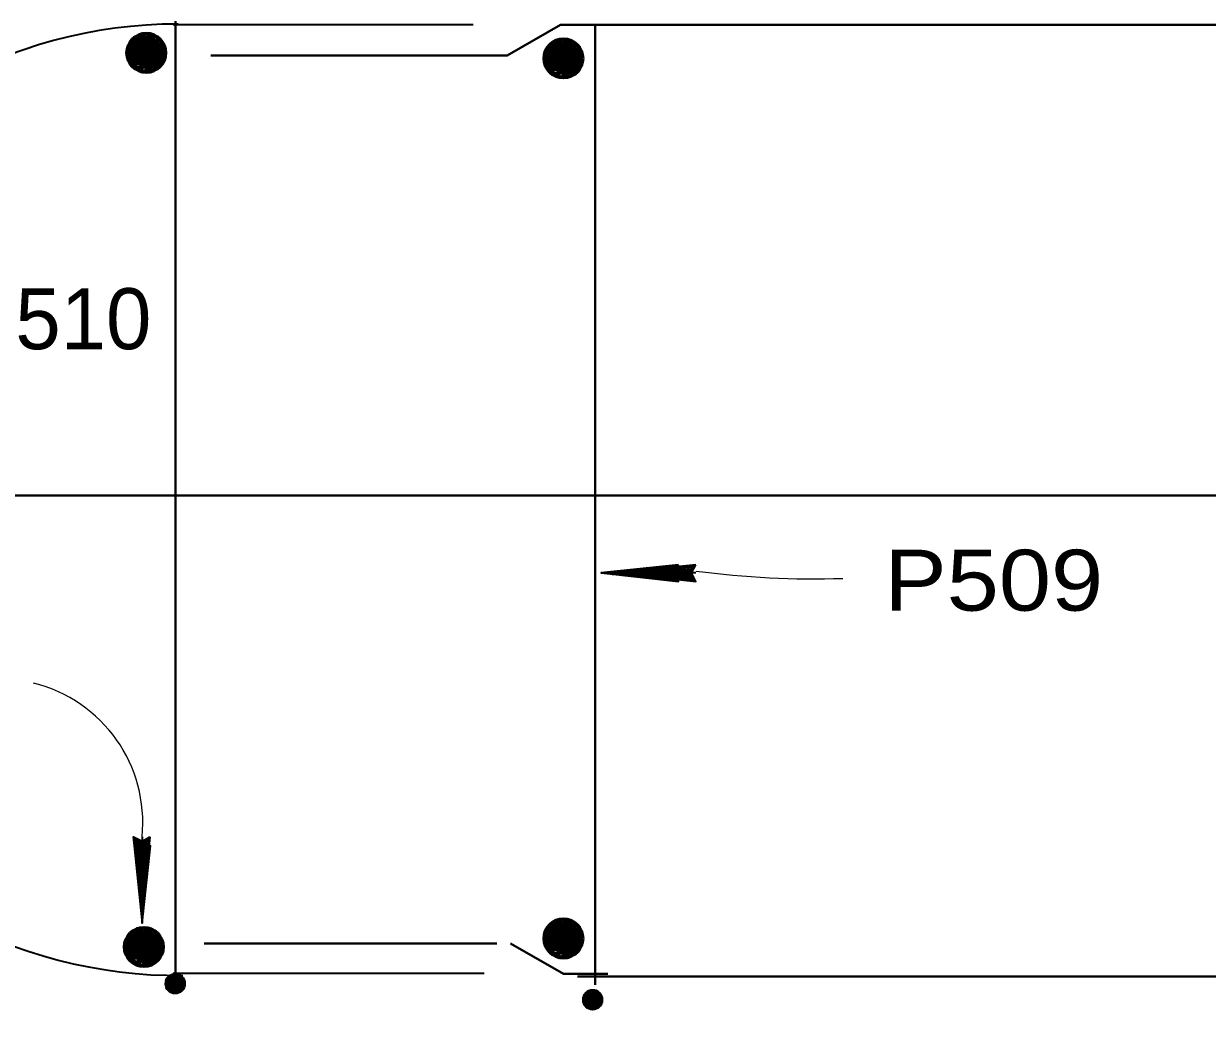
# Model space of a CAD drawing. Extents: x 3.64 to 6.84, y -0.8 to 1.19.
# Drawn here: x 4.0955 to 4.2572, y 0.714 to 0.852 of the extents above; entities that cross this region are included whole.
import ezdxf

# ---------------------------------------------------------------- set-up
doc = ezdxf.new("R2010")
doc.units = 0
doc.header["$LTSCALE"] = 0.0033
doc.layers.add('1', color=7, linetype='Continuous', lineweight=40)

msp = doc.modelspace()

# ---------------------------------------------------------------- linework, layer by layer
at = {"layer": '1', "lineweight": 35}
for p, q in [((4.115917, 0.851917), (4.156917, 0.851917)), ((4.185, 0.776917), (4.174417, 0.776917)), ((4.187333, 0.776917), (4.17675, 0.776917)), ((4.18475, 0.777917), (4.176917, 0.777)), ((4.18475, 0.777917), (4.176917, 0.777)), ((4.18475, 0.777833), (4.176917, 0.777)), ((4.18475, 0.77775), (4.176917, 0.776917)), ((4.18475, 0.77775), (4.176917, 0.77675)), ((4.18475, 0.776083), (4.177417, 0.776917)), ((4.18475, 0.776), (4.177417, 0.77675)), ((4.18475, 0.775833), (4.177417, 0.776667)), ((4.184833, 0.77625), (4.1775, 0.777)), ((4.187083, 0.777917), (4.17925, 0.777)), ((4.187083, 0.777917), (4.17925, 0.777)), ((4.187083, 0.777833), (4.17925, 0.777)), ((4.187083, 0.77775), (4.17925, 0.776917)), ((4.187083, 0.77775), (4.17925, 0.77675)), ((4.187083, 0.776083), (4.17975, 0.776917)), ((4.187083, 0.776), (4.17975, 0.77675)), ((4.187083, 0.775833), (4.17975, 0.776667)), ((4.187167, 0.77625), (4.179833, 0.777)), ((4.110583, 0.740583), (4.111417, 0.73325)), ((4.110667, 0.739333), (4.111583, 0.7315)), ((4.110667, 0.739333), (4.111583, 0.7315)), ((4.11075, 0.740583), (4.1115, 0.73325)), ((4.11075, 0.739333), (4.111583, 0.7315)), ((4.110833, 0.740583), (4.111667, 0.73325)), ((4.110833, 0.739333), (4.111667, 0.7315)), ((4.110833, 0.739333), (4.111833, 0.7315)), ((4.111, 0.740667), (4.11175, 0.733333)), ((4.1125, 0.740583), (4.1115, 0.73275)), ((4.112333, 0.739417), (4.111583, 0.732083)), ((4.111667, 0.740833), (4.111667, 0.73025)), ((4.1125, 0.740583), (4.111667, 0.73275)), ((4.111667, 0.739583), (4.111667, 0.729)), ((4.1125, 0.739333), (4.111667, 0.732)), ((4.112667, 0.740583), (4.11175, 0.73275)), ((4.112667, 0.740583), (4.11175, 0.73275)), ((4.112583, 0.740583), (4.11175, 0.73275)), ((4.112583, 0.739333), (4.111833, 0.732)), ((4.11275, 0.739333), (4.111917, 0.732)), ((4.115917, 0.722167), (4.158417, 0.722167))]:
    msp.add_line(p, q, dxfattribs=at)
at = {"layer": '1'}
for p, q in [((4.11625, 0.852333), (4.11625, 0.721)), ((4.173583, 0.851917), (4.173583, 0.720583)), ((4.110167, 0.849583), (4.11475, 0.847417)), ((4.1105, 0.849583), (4.114417, 0.848917)), ((4.1105, 0.849417), (4.114417, 0.848667)), ((4.110583, 0.849917), (4.114417, 0.84925)), ((4.1125, 0.849083), (4.113833, 0.850083)), ((4.114583, 0.84925), (4.113333, 0.850417)), ((4.1695, 0.848333), (4.170833, 0.849333)), ((4.171583, 0.8485), (4.170333, 0.849667)), ((4.110167, 0.84775), (4.114083, 0.847)), ((4.11025, 0.848167), (4.114083, 0.847417)), ((4.11025, 0.848), (4.114083, 0.84725)), ((4.110333, 0.848583), (4.114167, 0.847917)), ((4.110333, 0.848417), (4.114167, 0.847667)), ((4.110417, 0.849167), (4.114333, 0.848417)), ((4.110417, 0.849), (4.114333, 0.84825)), ((4.110417, 0.84875), (4.11425, 0.848)), ((4.167167, 0.848833), (4.17175, 0.846667)), ((4.167333, 0.847833), (4.171167, 0.847167)), ((4.167333, 0.847667), (4.171167, 0.846917)), ((4.167417, 0.848417), (4.171333, 0.847667)), ((4.167417, 0.84825), (4.171333, 0.8475)), ((4.167417, 0.848), (4.17125, 0.84725)), ((4.1675, 0.848833), (4.171417, 0.848167)), ((4.1675, 0.848667), (4.171417, 0.847917)), ((4.167583, 0.849167), (4.171417, 0.8485)), ((4.11, 0.846833), (4.113833, 0.846083)), ((4.11, 0.846667), (4.113833, 0.845917)), ((4.110083, 0.847333), (4.114, 0.846583)), ((4.110083, 0.847167), (4.113917, 0.846417)), ((4.110083, 0.846917), (4.113917, 0.84625)), ((4.114333, 0.846417), (4.110583, 0.846)), ((4.167, 0.846083), (4.170833, 0.845333)), ((4.167083, 0.846583), (4.171, 0.845833)), ((4.167083, 0.846417), (4.170917, 0.845667)), ((4.167083, 0.846167), (4.170917, 0.8455)), ((4.167167, 0.847), (4.171083, 0.84625)), ((4.16725, 0.847417), (4.171083, 0.846667)), ((4.16725, 0.84725), (4.171083, 0.8465)), ((4.167, 0.845917), (4.170833, 0.845167)), ((4.171333, 0.845667), (4.167583, 0.84525)), ((4.050917, 0.7875), (4.474833, 0.7875)), ((4.11425, 0.727), (4.113, 0.728167)), ((4.167167, 0.7285), (4.17175, 0.726333)), ((4.167417, 0.728083), (4.171333, 0.727333)), ((4.167417, 0.727917), (4.171333, 0.727167)), ((4.1675, 0.7285), (4.171417, 0.727833)), ((4.1675, 0.728333), (4.171417, 0.727583)), ((4.167583, 0.728833), (4.171417, 0.728167)), ((4.1695, 0.728), (4.170833, 0.729)), ((4.171583, 0.728167), (4.170333, 0.729333)), ((4.109833, 0.727333), (4.114417, 0.725167)), ((4.11, 0.726333), (4.113833, 0.725667)), ((4.110083, 0.726917), (4.114, 0.726167)), ((4.110083, 0.72675), (4.114, 0.726)), ((4.110083, 0.7265), (4.113917, 0.72575)), ((4.110167, 0.727333), (4.114083, 0.726667)), ((4.110167, 0.727167), (4.114083, 0.726417)), ((4.11025, 0.727667), (4.114083, 0.727)), ((4.112167, 0.726833), (4.1135, 0.727833)), ((4.167167, 0.726667), (4.171083, 0.725917)), ((4.16725, 0.727083), (4.171083, 0.726333)), ((4.16725, 0.726917), (4.171083, 0.726167)), ((4.167333, 0.7275), (4.171167, 0.726833)), ((4.167333, 0.727333), (4.171167, 0.726583)), ((4.167417, 0.727667), (4.17125, 0.726917)), ((4.10975, 0.725083), (4.113667, 0.724333)), ((4.10975, 0.724917), (4.113583, 0.724167)), ((4.109833, 0.7255), (4.11375, 0.72475)), ((4.109917, 0.725917), (4.11375, 0.725167)), ((4.109917, 0.72575), (4.11375, 0.725)), ((4.11, 0.726167), (4.113833, 0.725417)), ((4.120167, 0.72625), (4.160167, 0.72625)), ((4.167, 0.72575), (4.170833, 0.725)), ((4.167, 0.725583), (4.170833, 0.724833)), ((4.167083, 0.72625), (4.171, 0.7255)), ((4.167083, 0.726083), (4.170917, 0.725333)), ((4.167083, 0.725833), (4.170917, 0.725167)), ((4.171333, 0.725333), (4.167583, 0.724917)), ((4.109667, 0.724583), (4.1135, 0.723833)), ((4.109667, 0.724417), (4.1135, 0.723667)), ((4.10975, 0.724667), (4.113583, 0.724)), ((4.114, 0.724167), (4.11025, 0.72375)), ((4.11525, 0.721583), (4.115583, 0.719667)), ((4.115417, 0.721667), (4.116917, 0.72175)), ((4.115417, 0.721583), (4.116917, 0.721667)), ((4.115417, 0.721667), (4.11575, 0.719667)), ((4.115417, 0.7215), (4.116917, 0.721583)), ((4.115417, 0.721417), (4.116917, 0.7215)), ((4.1155, 0.721667), (4.115833, 0.719667)), ((4.115583, 0.721667), (4.116, 0.719667)), ((4.115667, 0.721667), (4.116083, 0.719667)), ((4.115833, 0.721667), (4.116167, 0.71975)), ((4.115917, 0.72175), (4.11625, 0.71975)), ((4.116, 0.72175), (4.116417, 0.71975)), ((4.116083, 0.72175), (4.1165, 0.719833)), ((4.116167, 0.72175), (4.116583, 0.719833)), ((4.116333, 0.721833), (4.11675, 0.719833)), ((4.116583, 0.721833), (4.116917, 0.719833)), ((4.116667, 0.721833), (4.117, 0.719917)), ((4.11675, 0.721833), (4.117083, 0.719917)), ((4.116833, 0.721917), (4.117167, 0.719917)), ((4.39375, 0.72175), (4.171167, 0.72175)), ((4.115417, 0.721333), (4.116917, 0.721417)), ((4.115417, 0.721167), (4.116917, 0.72125)), ((4.115417, 0.721083), (4.116917, 0.721167)), ((4.115417, 0.721), (4.116917, 0.721083)), ((4.115417, 0.720917), (4.116917, 0.721)), ((4.115417, 0.720833), (4.116917, 0.720917)), ((4.115417, 0.72075), (4.116917, 0.720833)), ((4.115417, 0.720667), (4.116917, 0.72075)), ((4.1155, 0.7205), (4.117, 0.720667)), ((4.1155, 0.720333), (4.117, 0.7205)), ((4.1155, 0.72025), (4.117, 0.720333)), ((4.1155, 0.72025), (4.117, 0.720333)), ((4.1155, 0.720167), (4.117, 0.72025)), ((4.1155, 0.720083), (4.117, 0.720167)), ((4.1155, 0.72), (4.117, 0.720083)), ((4.1155, 0.719917), (4.117, 0.72)), ((4.1155, 0.719833), (4.117, 0.719917)), ((4.1155, 0.71975), (4.117, 0.719833)), ((4.1155, 0.719583), (4.117, 0.719667)), ((4.172083, 0.71925), (4.172167, 0.71775)), ((4.174083, 0.7195), (4.172167, 0.719167)), ((4.174167, 0.719333), (4.172167, 0.719)), ((4.174167, 0.71925), (4.172167, 0.718917)), ((4.174167, 0.719167), (4.172167, 0.71875)), ((4.174167, 0.719083), (4.172167, 0.718667)), ((4.17225, 0.71925), (4.172333, 0.71775)), ((4.174167, 0.718917), (4.17225, 0.718583)), ((4.17425, 0.718833), (4.17225, 0.7185)), ((4.17425, 0.71875), (4.17225, 0.718333)), ((4.172333, 0.71925), (4.172417, 0.71775)), ((4.17425, 0.718667), (4.172333, 0.71825)), ((4.17425, 0.718583), (4.172333, 0.718167)), ((4.174333, 0.718417), (4.172333, 0.718)), ((4.172417, 0.71925), (4.1725, 0.71775)), ((4.1725, 0.71925), (4.172583, 0.71775)), ((4.172583, 0.71925), (4.172667, 0.71775)), ((4.172667, 0.71925), (4.17275, 0.71775)), ((4.17275, 0.71925), (4.172833, 0.71775)), ((4.17275, 0.71925), (4.172833, 0.71775)), ((4.172833, 0.71925), (4.173, 0.71775)), ((4.173, 0.71925), (4.173167, 0.71775)), ((4.173167, 0.719333), (4.17325, 0.717833)), ((4.17325, 0.719333), (4.173333, 0.717833)), ((4.173333, 0.719333), (4.173417, 0.717833)), ((4.173417, 0.719333), (4.1735, 0.717833)), ((4.1735, 0.719333), (4.173583, 0.717833)), ((4.173583, 0.719333), (4.173667, 0.717833)), ((4.173667, 0.719333), (4.17375, 0.717833)), ((4.173833, 0.719333), (4.173917, 0.717833)), ((4.173917, 0.719333), (4.174, 0.717833)), ((4.174, 0.719333), (4.174083, 0.717833)), ((4.174083, 0.719333), (4.174167, 0.717833)), ((4.174167, 0.719333), (4.17425, 0.717833)), ((4.174333, 0.718167), (4.172333, 0.717833)), ((4.174333, 0.718083), (4.172417, 0.71775)), ((4.174333, 0.718), (4.172417, 0.717667)), ((4.174417, 0.717917), (4.172417, 0.717583))]:
    msp.add_line(p, q, dxfattribs=at)
at = {"layer": '1', "lineweight": 60}
for p, q in [((4.110417, 0.849583), (4.11025, 0.846667)), ((4.110667, 0.849583), (4.110417, 0.846667)), ((4.110833, 0.849583), (4.110667, 0.846583)), ((4.111, 0.849583), (4.11075, 0.846583)), ((4.111167, 0.849583), (4.111, 0.846583)), ((4.111417, 0.849583), (4.11125, 0.846583)), ((4.111667, 0.849583), (4.111417, 0.846583)), ((4.11175, 0.8495), (4.111583, 0.846583)), ((4.111917, 0.8495), (4.11175, 0.846583)), ((4.112083, 0.8495), (4.111917, 0.846583)), ((4.112333, 0.8495), (4.112083, 0.846583)), ((4.1125, 0.8495), (4.112333, 0.846583)), ((4.11275, 0.849417), (4.1125, 0.8465)), ((4.113, 0.849417), (4.11275, 0.8465)), ((4.113167, 0.849417), (4.113, 0.8465)), ((4.11325, 0.849417), (4.113083, 0.8465)), ((4.113417, 0.849417), (4.11325, 0.8465)), ((4.1135, 0.849417), (4.113333, 0.8465)), ((4.11375, 0.849333), (4.1135, 0.846417)), ((4.113917, 0.849333), (4.11375, 0.846417)), ((4.114083, 0.849333), (4.113833, 0.846417)), ((4.11425, 0.849333), (4.114083, 0.846417)), ((4.1145, 0.849333), (4.114333, 0.846417)), ((4.11475, 0.847417), (4.114583, 0.84925)), ((4.167417, 0.848833), (4.16725, 0.845917)), ((4.167667, 0.848833), (4.167417, 0.845917)), ((4.167833, 0.848833), (4.167667, 0.845833)), ((4.168, 0.848833), (4.16775, 0.845833)), ((4.168167, 0.848833), (4.168, 0.845833)), ((4.168417, 0.848833), (4.16825, 0.845833)), ((4.168667, 0.848833), (4.168417, 0.845833)), ((4.16875, 0.84875), (4.168583, 0.845833)), ((4.168917, 0.84875), (4.16875, 0.845833)), ((4.169083, 0.84875), (4.168917, 0.845833)), ((4.169333, 0.84875), (4.169083, 0.845833)), ((4.1695, 0.84875), (4.169333, 0.845833)), ((4.16975, 0.848667), (4.1695, 0.84575)), ((4.17, 0.848667), (4.16975, 0.84575)), ((4.170167, 0.848667), (4.17, 0.84575)), ((4.17025, 0.848667), (4.170083, 0.84575)), ((4.170417, 0.848667), (4.17025, 0.84575)), ((4.1705, 0.848667), (4.170333, 0.84575)), ((4.17075, 0.848583), (4.1705, 0.845667)), ((4.170917, 0.848583), (4.17075, 0.845667)), ((4.171083, 0.848583), (4.170833, 0.845667)), ((4.17125, 0.848583), (4.171083, 0.845667)), ((4.1715, 0.848583), (4.171333, 0.845667)), ((4.17175, 0.846667), (4.171583, 0.8485)), ((4.11475, 0.847417), (4.11, 0.846667)), ((4.17175, 0.846667), (4.167, 0.845917)), ((4.167417, 0.7285), (4.16725, 0.725583)), ((4.167667, 0.7285), (4.167417, 0.725583)), ((4.167833, 0.7285), (4.167667, 0.7255)), ((4.168, 0.7285), (4.16775, 0.7255)), ((4.168167, 0.7285), (4.168, 0.7255)), ((4.168417, 0.7285), (4.16825, 0.7255)), ((4.168667, 0.7285), (4.168417, 0.7255)), ((4.16875, 0.728417), (4.168583, 0.7255)), ((4.168917, 0.728417), (4.16875, 0.7255)), ((4.169083, 0.728417), (4.168917, 0.7255)), ((4.169333, 0.728417), (4.169083, 0.7255)), ((4.1695, 0.728417), (4.169333, 0.7255)), ((4.16975, 0.728333), (4.1695, 0.725417)), ((4.17, 0.728333), (4.16975, 0.725417)), ((4.170167, 0.728333), (4.17, 0.725417)), ((4.17025, 0.728333), (4.170083, 0.725417)), ((4.170417, 0.728333), (4.17025, 0.725417)), ((4.1705, 0.728333), (4.170333, 0.725417)), ((4.17075, 0.72825), (4.1705, 0.725333)), ((4.170917, 0.72825), (4.17075, 0.725333)), ((4.171083, 0.72825), (4.170833, 0.725333)), ((4.17125, 0.72825), (4.171083, 0.725333)), ((4.1715, 0.72825), (4.171333, 0.725333)), ((4.17175, 0.726333), (4.171583, 0.728167)), ((4.110083, 0.727333), (4.109917, 0.724417)), ((4.110333, 0.727333), (4.110083, 0.724417)), ((4.1105, 0.727333), (4.110333, 0.724333)), ((4.110667, 0.727333), (4.110417, 0.724333)), ((4.110833, 0.727333), (4.110667, 0.724333)), ((4.111083, 0.727333), (4.110917, 0.724333)), ((4.111333, 0.727333), (4.111083, 0.724333)), ((4.111417, 0.72725), (4.11125, 0.724333)), ((4.111583, 0.72725), (4.111417, 0.724333)), ((4.11175, 0.72725), (4.111583, 0.724333)), ((4.112, 0.72725), (4.11175, 0.724333)), ((4.112167, 0.72725), (4.112, 0.724333)), ((4.112417, 0.727167), (4.112167, 0.72425)), ((4.112667, 0.727167), (4.112417, 0.72425)), ((4.112833, 0.727167), (4.112667, 0.72425)), ((4.112917, 0.727167), (4.11275, 0.72425)), ((4.113083, 0.727167), (4.112917, 0.72425)), ((4.113167, 0.727167), (4.113, 0.72425)), ((4.113417, 0.727083), (4.113167, 0.724167)), ((4.113583, 0.727083), (4.113417, 0.724167)), ((4.11375, 0.727083), (4.1135, 0.724167)), ((4.113917, 0.727083), (4.11375, 0.724167)), ((4.114167, 0.727083), (4.114, 0.724167)), ((4.114417, 0.725167), (4.11425, 0.727)), ((4.17175, 0.726333), (4.167, 0.725583)), ((4.114417, 0.725167), (4.109667, 0.724417))]:
    msp.add_line(p, q, dxfattribs=at)
at = {"layer": '1'}
for points in [[(4.121083, 0.847667), (4.161583, 0.847667), (4.168833, 0.851833), (4.398667, 0.851833)], [(4.11, 0.846667), (4.112083, 0.845417), (4.113833, 0.845917), (4.11475, 0.847417)], [(4.167, 0.845917), (4.169083, 0.844667), (4.170833, 0.845167), (4.17175, 0.846667)], [(4.254417, 0.7875), (4.175833, 0.7875), (4.0545, 0.7875)], [(4.167, 0.725583), (4.169083, 0.724333), (4.170833, 0.724833), (4.17175, 0.726333)], [(4.109667, 0.724417), (4.11175, 0.723167), (4.1135, 0.723667), (4.114417, 0.725167)], [(4.162, 0.72625), (4.16925, 0.722083), (4.175333, 0.722083)], [(4.11625, 0.722083), (4.115917, 0.7195), (4.115417, 0.721833), (4.1165, 0.7195), (4.116917, 0.721917), (4.11725, 0.719917), (4.115167, 0.719917), (4.1175, 0.720833), (4.114917, 0.720583), (4.11725, 0.721583), (4.114917, 0.72125), (4.1175, 0.720417), (4.11575, 0.722), (4.115583, 0.719583), (4.117417, 0.72125), (4.115, 0.720167), (4.115417, 0.721833), (4.116917, 0.721917), (4.1175, 0.720833), (4.11725, 0.719917), (4.1165, 0.7195), (4.115583, 0.719583), (4.115, 0.720167), (4.116083, 0.720833), (4.117, 0.719667), (4.11725, 0.721583), (4.116083, 0.720833), (4.115583, 0.721917), (4.114917, 0.720917), (4.116, 0.720833), (4.11725, 0.72), (4.116, 0.722), (4.115667, 0.720667), (4.115167, 0.719917)], [(4.174583, 0.7185), (4.172, 0.718833), (4.174333, 0.719333), (4.172, 0.71825), (4.174417, 0.717833), (4.172417, 0.7175), (4.172417, 0.719583), (4.173333, 0.71725), (4.173083, 0.719833), (4.174083, 0.7175), (4.17375, 0.719833), (4.172917, 0.71725), (4.1745, 0.719), (4.172083, 0.719167), (4.17375, 0.717333), (4.172667, 0.71975), (4.174333, 0.719333), (4.174417, 0.717833), (4.173333, 0.71725), (4.172417, 0.7175), (4.172, 0.71825), (4.172083, 0.719167), (4.172667, 0.71975), (4.173333, 0.718667), (4.172167, 0.71775), (4.174083, 0.7175), (4.173333, 0.718667), (4.174417, 0.719167), (4.173417, 0.719833), (4.173333, 0.71875), (4.1725, 0.7175), (4.1745, 0.71875), (4.173167, 0.719083), (4.172417, 0.719583)]]:
    msp.add_lwpolyline(points, dxfattribs=at)
at = {"layer": '1', "lineweight": 60}
for points in [[(4.109583, 0.847917), (4.11475, 0.848583), (4.110167, 0.849583)], [(4.113833, 0.845917), (4.113833, 0.850083), (4.112167, 0.845417), (4.112667, 0.850583), (4.110583, 0.846), (4.111333, 0.8505), (4.112917, 0.8455), (4.10975, 0.848833), (4.114583, 0.84925), (4.111333, 0.845583), (4.113333, 0.850417), (4.110167, 0.849583), (4.11, 0.846667)], [(4.110583, 0.846), (4.112083, 0.84825), (4.109917, 0.849167), (4.111917, 0.850583), (4.112083, 0.848333), (4.11375, 0.846), (4.10975, 0.848333), (4.1125, 0.849083)], [(4.113333, 0.850417), (4.112083, 0.84825), (4.114333, 0.846417)], [(4.170833, 0.845167), (4.170833, 0.849333), (4.169167, 0.844667), (4.169667, 0.849833), (4.167583, 0.84525), (4.168333, 0.84975), (4.169917, 0.84475), (4.16675, 0.848083), (4.171583, 0.8485), (4.168333, 0.844833), (4.170333, 0.849667), (4.167167, 0.848833), (4.167, 0.845917)], [(4.167583, 0.84525), (4.169083, 0.8475), (4.166917, 0.848417), (4.168917, 0.849833), (4.169083, 0.847583), (4.17075, 0.84525), (4.16675, 0.847583), (4.1695, 0.848333)], [(4.170333, 0.849667), (4.169083, 0.8475), (4.171333, 0.845667)], [(4.166583, 0.847167), (4.17175, 0.847833), (4.167167, 0.848833)], [(4.1135, 0.723667), (4.1135, 0.727833), (4.111833, 0.723167), (4.112333, 0.728333), (4.11025, 0.72375), (4.111, 0.72825), (4.112583, 0.72325), (4.109417, 0.726583), (4.11425, 0.727), (4.111, 0.723333), (4.113, 0.728167), (4.109833, 0.727333), (4.109667, 0.724417)], [(4.11025, 0.72375), (4.11175, 0.726), (4.109583, 0.726917), (4.111583, 0.728333), (4.11175, 0.726083), (4.113417, 0.72375), (4.109417, 0.726083), (4.112167, 0.726833)], [(4.113, 0.728167), (4.11175, 0.726), (4.114, 0.724167)], [(4.166583, 0.726833), (4.17175, 0.7275), (4.167167, 0.7285)], [(4.170833, 0.724833), (4.170833, 0.729), (4.169167, 0.724333), (4.169667, 0.7295), (4.167583, 0.724917), (4.168333, 0.729417), (4.169917, 0.724417), (4.16675, 0.72775), (4.171583, 0.728167), (4.168333, 0.7245), (4.170333, 0.729333), (4.167167, 0.7285), (4.167, 0.725583)], [(4.167583, 0.724917), (4.169083, 0.727167), (4.166917, 0.728083), (4.168917, 0.7295), (4.169083, 0.72725), (4.17075, 0.724917), (4.16675, 0.72725), (4.1695, 0.728)], [(4.170333, 0.729333), (4.169083, 0.727167), (4.171333, 0.725333)], [(4.10925, 0.725667), (4.114417, 0.726333), (4.109833, 0.727333)]]:
    msp.add_lwpolyline(points, dxfattribs=at)
at = {"layer": '1', "lineweight": 35}
for points in [[(4.185, 0.778), (4.174417, 0.776917), (4.185, 0.77575), (4.184417, 0.776917)], [(4.18425, 0.777), (4.179583, 0.777083), (4.179583, 0.777), (4.1805, 0.777), (4.18425, 0.777083), (4.18125, 0.777167), (4.184417, 0.77725), (4.182167, 0.777333), (4.184417, 0.777417), (4.180917, 0.777167), (4.17625, 0.777), (4.177167, 0.77675), (4.175917, 0.77675), (4.18425, 0.77675), (4.181833, 0.776583), (4.184417, 0.776583), (4.179083, 0.777), (4.184417, 0.776333)], [(4.187333, 0.778), (4.17675, 0.776917), (4.187333, 0.77575), (4.18675, 0.776917)], [(4.186583, 0.777), (4.181917, 0.777083), (4.181917, 0.777), (4.182833, 0.777), (4.186583, 0.777083), (4.183583, 0.777167), (4.18675, 0.77725), (4.1845, 0.777333), (4.18675, 0.777417), (4.18325, 0.777167), (4.178583, 0.777), (4.1795, 0.77675), (4.17825, 0.77675), (4.186583, 0.77675), (4.184167, 0.776583), (4.18675, 0.776583), (4.181417, 0.777), (4.18675, 0.776333)], [(4.11275, 0.740833), (4.111667, 0.73025), (4.1105, 0.740833), (4.111667, 0.74025)], [(4.110583, 0.739583), (4.111667, 0.729), (4.112833, 0.739583), (4.111667, 0.739)], [(4.11175, 0.740083), (4.111833, 0.735417), (4.11175, 0.735417), (4.11175, 0.736333), (4.111833, 0.740083), (4.111917, 0.737083), (4.112, 0.74025), (4.112083, 0.738), (4.112167, 0.74025), (4.111917, 0.73675), (4.11175, 0.732083), (4.1115, 0.733), (4.1115, 0.73175), (4.1115, 0.740083), (4.111333, 0.737667), (4.111333, 0.74025), (4.11175, 0.734917), (4.111083, 0.74025)], [(4.111583, 0.738833), (4.1115, 0.734167), (4.111583, 0.734167), (4.111583, 0.735083), (4.1115, 0.738833), (4.111417, 0.735833), (4.111333, 0.739), (4.11125, 0.73675), (4.111167, 0.739), (4.111417, 0.7355), (4.111583, 0.730833), (4.111833, 0.73175), (4.111833, 0.7305), (4.111833, 0.738833), (4.112, 0.736417), (4.112, 0.739), (4.111583, 0.733667), (4.11225, 0.739)]]:
    msp.add_lwpolyline(points, close=True, dxfattribs=at)
for points in [[(4.18425, 0.777), (4.184667, 0.77775), (4.184417, 0.7775), (4.18425, 0.777167), (4.184, 0.77725), (4.184167, 0.777583), (4.184333, 0.776833), (4.1845, 0.776333), (4.18475, 0.775917)], [(4.186583, 0.777), (4.187, 0.77775), (4.18675, 0.7775), (4.186583, 0.777167), (4.186333, 0.77725), (4.1865, 0.777583), (4.186667, 0.776833), (4.186833, 0.776333), (4.187083, 0.775917)], [(4.11175, 0.740083), (4.1125, 0.7405), (4.11225, 0.74025), (4.111917, 0.740083), (4.112, 0.739833), (4.112333, 0.74), (4.111583, 0.740167), (4.111083, 0.740333), (4.110667, 0.740583)], [(4.111583, 0.738833), (4.110833, 0.73925), (4.111083, 0.739), (4.111417, 0.738833), (4.111333, 0.738583), (4.111, 0.73875), (4.11175, 0.738917), (4.11225, 0.739083), (4.112667, 0.739333)]]:
    msp.add_lwpolyline(points, dxfattribs=at)
at = {"layer": '1', "lineweight": 60}
for centre in [(4.11225, 0.848017), (4.16925, 0.847267), (4.16925, 0.726933), (4.111917, 0.725767)]:
    msp.add_circle(centre, 0.00264, dxfattribs=at)
at = {"layer": '1'}
for centre in [(4.1162, 0.72075), (4.17325, 0.71855)]:
    msp.add_circle(centre, 0.00132, dxfattribs=at)
at = {"layer": '1', "lineweight": 60}
msp.add_arc((4.115333, 0.785667), 0.082833, 97.64809, 263.01663, dxfattribs=at)
at = {"layer": '1', "lineweight": 35}
msp.add_arc((4.116583, 0.786917), 0.065042, 90, 270.57654, dxfattribs=at)
at = {"layer": '1', "lineweight": 13}
for centre, radius, start, end in [((4.20341, 0.896531), 0.120431, 262.36857, 271.90662), ((4.092171, 0.742801), 0.019595, 354.23615, 76.23474)]:
    msp.add_arc(centre, radius, start, end, dxfattribs=at)

# ---------------------------------------------------------------- texts
at = {"layer": '1'}
msp.add_text('P510', height=0.008334, dxfattribs=at).set_placement((4.086917, 0.8075))
at = {"layer": '1', "width": 1.15}
msp.add_text('P509', height=0.008334, dxfattribs=at).set_placement((4.213083, 0.77175))

doc.saveas('drawing.dxf')
